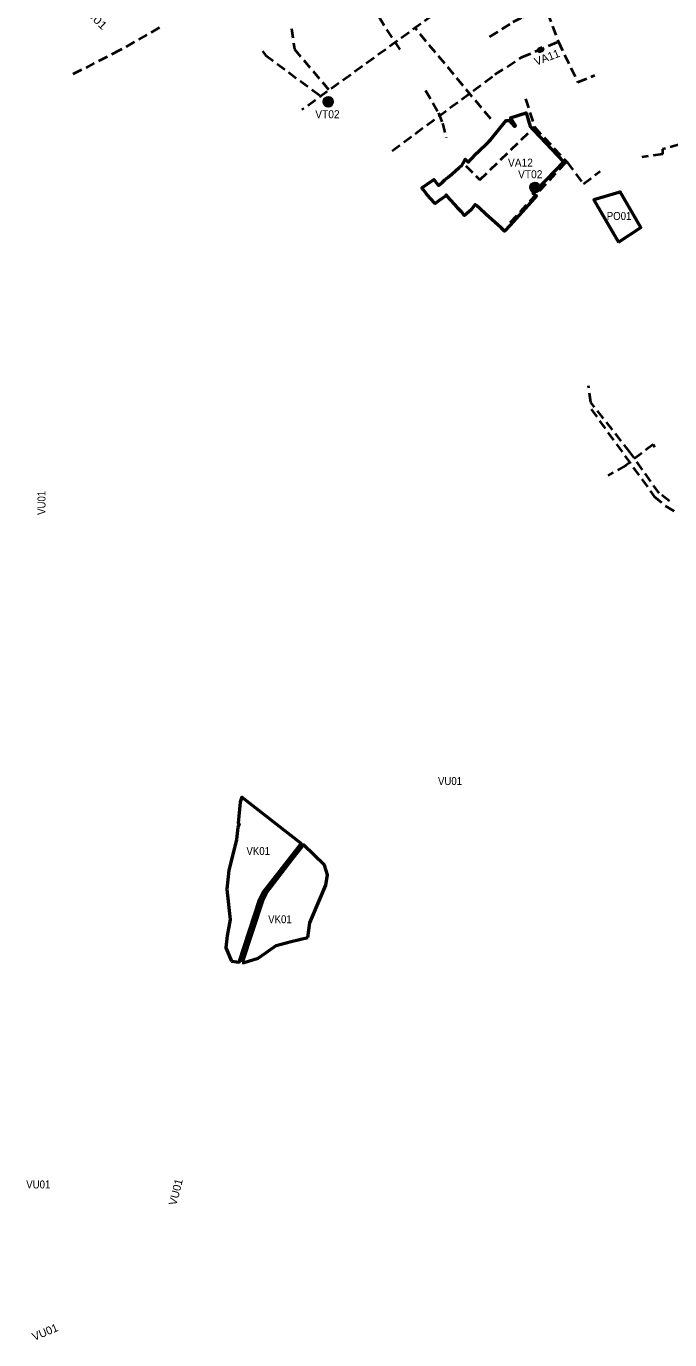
# Model space of a CAD drawing. Extents: x -650145 to -642675, y -1074338 to -1066803.
# Drawn here: x -648976 to -647369, y -1074338 to -1071056 of the extents above; entities that cross this region are included whole.
import ezdxf

# ---------------------------------------------------------------- set-up
doc = ezdxf.new("R2010")
doc.units = 0
doc.header["$LTSCALE"] = 8
doc.linetypes.add('MEDIUM_DASHED', pattern=[4.5, 3, -1.5])
for name, color, linetype in [('1', 7, 'Continuous'), ('17', 7, 'Continuous'), ('2', 7, 'Continuous'), ('3', 7, 'Continuous'), ('4', 7, 'Continuous')]:
    doc.layers.add(name, color=color, linetype=linetype)
for name, color, linetype, lineweight in [('12', 7, 'MEDIUM_DASHED', 40), ('15', 7, 'Continuous', 13), ('45', 7, 'Continuous', 53), ('46', 7, 'Continuous', 53), ('60', 7, 'Continuous', 53)]:
    doc.layers.add(name, color=color, linetype=linetype, lineweight=lineweight)

msp = doc.modelspace()

# ---------------------------------------------------------------- hatches: boundary and pattern name
at = {"layer": '15'}
for points in [[(-648210.363, -1071245, 1), (-648233.888, -1071245, 1)], [(-647694.212, -1071458.99, 1), (-647717.737, -1071458.99, 1)]]:
    msp.add_hatch(color=256, dxfattribs=at).paths.add_polyline_path(points)
at = {"layer": '60'}
msp.add_hatch(color=256, dxfattribs=at).paths.add_polyline_path([(-647687.68, -1071110.18), (-647696.64, -1071114.02), (-647694.63, -1071118.73), (-647685.66, -1071114.89)])

# ---------------------------------------------------------------- linework, layer by layer
at = {"layer": '12'}
for p, q in [((-648042.555, -1071114.098), (-648099.428, -1071026.867)), ((-647815.949, -1071287.658), (-648004.905, -1071060.503)), ((-647767.223, -1071546.187), (-647626.359, -1071394.366))]:
    msp.add_line(p, q, dxfattribs=at)
for points in [[(-647794.16, -1070745.19), (-647787.83, -1070767.157), (-647743.987, -1070862.016), (-647758.284, -1070869.702), (-647784.836, -1070875.103), (-647850.393, -1070906.456), (-647898.698, -1070936.31), (-647903.521, -1070987.043), (-648287.54, -1071265.293)], [(-647818.707, -1071082.607), (-647759.543, -1071045.17), (-647733.735, -1071032.504), (-647710.774, -1071025.971), (-647674.039, -1071022.323), (-647646.98, -1071094.735)], [(-648643.705, -1071059.314), (-648742.207, -1071116.062), (-648865.074, -1071178.477)], [(-648313.283, -1071061.443), (-648306.336, -1071112.945), (-648219.799, -1071215.376)], [(-648062.403, -1071367.342), (-647805.426, -1071176.999), (-647738.219, -1071133.017), (-647646.98, -1071094.735), (-647598.326, -1071195.826), (-647556.251, -1071178.604)], [(-648386.1, -1071118.4), (-648378.803, -1071128.097), (-648240.257, -1071231.033)], [(-647978.731, -1071216.254), (-647946.561, -1071272.093), (-647936.852, -1071298.253), (-647926.931, -1071334.225)], [(-647728.988, -1071237.115), (-647707.004, -1071307.776), (-647625.351, -1071395.71), (-647584.501, -1071450.177), (-647542.285, -1071418.425)], [(-647878.3, -1071404.7), (-647843.135, -1071439.808), (-647707.004, -1071307.776)], [(-647344.33, -1071351.49), (-647386.85, -1071363.37), (-647386.8, -1071375.58), (-647438.34, -1071382.93)], [(-647369.65, -1072242.58), (-647395.603, -1072222.827), (-647467.645, -1072120.835), (-647565.59, -1071996.178), (-647571.937, -1071954.126)], [(-647565.274, -1072012.581), (-647407.42, -1072230.889), (-647378.312, -1072255.368), (-647327.486, -1072284.458), (-647289.597, -1072293.583), (-647241.628, -1072293.997), (-647186.201, -1072273.818), (-647145.51, -1072238.04)], [(-647405.694, -1072108.1), (-647409.897, -1072100.921), (-647478.896, -1072153.329), (-647523.403, -1072178.874)]]:
    msp.add_lwpolyline(points, dxfattribs=at)
at = {"layer": '15', "lineweight": 35}
for centre in [(-648222.125, -1071245), (-647705.974, -1071458.99)]:
    msp.add_circle(centre, 11.762, dxfattribs=at)
at = {"layer": '45'}
for points in [[(-648463.25, -1073392.125), (-648444.523, -1073394.235), (-648392.43, -1073235.98), (-648384.6, -1073219.54), (-648315.955, -1073131.889), (-648289.148, -1073097.66), (-648437.643, -1072982.601), (-648442.187, -1072994.5), (-648447.043, -1073046.967), (-648444.11, -1073048.69), (-648448.1, -1073058.393)], [(-648448.1, -1073058.393), (-648450.875, -1073088.375), (-648469.875, -1073165.5), (-648475.437, -1073212.375), (-648466.687, -1073288.25), (-648474.5, -1073328.75), (-648477.562, -1073358.875), (-648463.25, -1073392.125)], [(-648272.642, -1073332.558), (-648268, -1073296), (-648261, -1073280), (-648228, -1073202), (-648224, -1073176), (-648231, -1073152), (-648283.884, -1073101.15), (-648311.798, -1073137.127), (-648378.17, -1073222.67), (-648385.09, -1073238.58), (-648436.857, -1073395.099)], [(-648397.062, -1073384.375), (-648378.125, -1073370.875), (-648352.312, -1073353), (-648314.687, -1073343.25), (-648272.642, -1073332.558)], [(-648436.857, -1073395.099), (-648432.187, -1073395.625), (-648397.062, -1073384.375)]]:
    msp.add_lwpolyline(points, dxfattribs=at)
at = {"layer": '46'}
msp.add_lwpolyline([(-647497.04, -1071595.66), (-647440.67, -1071558.93), (-647492.3, -1071470), (-647495.85, -1071471.06), (-647558.654, -1071489.738)], close=True, dxfattribs=at)
at = {"layer": '60'}
for points in [[(-647687.68, -1071110.18), (-647696.64, -1071114.02), (-647694.63, -1071118.73), (-647685.66, -1071114.89)], [(-647777.4, -1071291.32), (-647777.4, -1071291.32), (-647774.14, -1071291.34), (-647769.85, -1071291.91), (-647756.67, -1071306.77), (-647753.89, -1071303.94), (-647766.35, -1071285.11), (-647727.368, -1071272.362), (-647717.363, -1071306.29), (-647708.429, -1071316.821), (-647634.524, -1071394.901), (-647700.078, -1071462.96), (-647710.546, -1071472.023), (-647704.78, -1071477.1), (-647701.415, -1071480.15), (-647708.18, -1071487.57), (-647767.575, -1071553.083), (-647781.31, -1071567.79), (-647789.73, -1071560.1), (-647828.024, -1071525.256), (-647844.4, -1071510.2), (-647850.55, -1071505.14), (-647855.23, -1071501.297), (-647860.576, -1071508.843), (-647864.69, -1071514.65), (-647869.922, -1071519.269), (-647876.29, -1071524.89), (-647881.16, -1071529.25), (-647883.31, -1071526.83), (-647889.29, -1071520.11), (-647897.27, -1071511.15), (-647905.25, -1071502.19), (-647917.23, -1071488.75), (-647927.2, -1071477.54), (-647929.26, -1071480.77), (-647931.17, -1071482.12), (-647936.59, -1071485.96), (-647944.81, -1071491.78), (-647955.14, -1071499.23), (-647967.13, -1071486.01), (-647972.76, -1071479), (-647977.13, -1071474.05), (-647984.07, -1071465.1), (-647987.8, -1071459.68), (-647961.4, -1071441.47), (-647957.906, -1071439.06), (-647946.78, -1071454.23), (-647937.43, -1071446.16), (-647930.38, -1071440.08), (-647921.96, -1071432.81), (-647913.31, -1071425.35), (-647904.3, -1071417.58), (-647895.29, -1071409.81), (-647888.11, -1071403.61), (-647885.05, -1071397.88), (-647879.76, -1071387.96), (-647871.68, -1071395.59), (-647867.45, -1071390.95), (-647849.86, -1071372.18), (-647820.93, -1071344.25), (-647815.474, -1071339.22)]]:
    msp.add_lwpolyline(points, close=True, dxfattribs=at)

# ---------------------------------------------------------------- texts
at = {"layer": '1', "width": 0.9}
for p in [(-648426.286, -1073126.802), (-648372.004, -1073297.285)]:
    msp.add_text('VK01', height=20, dxfattribs=at).set_placement(p)
at = {"layer": '17', "width": 0.95}
for p in [(-648254.236, -1071285.892), (-647747.641, -1071435.784)]:
    msp.add_text('VT02', height=20, dxfattribs=at).set_placement(p)
at = {"layer": '2'}
for rotation, width, p in [(315.876, 1.2, (-648843.543, -1071010.613)), (90, 0.9, (-648928.323, -1072276.985))]:
    msp.add_text('VU01', height=20, rotation=rotation, dxfattribs=dict(at, width=width)).set_placement(p)
at = {"layer": '2', "width": 0.9}
for p in [(-647947.746, -1072951.906), (-648976.371, -1073959.861)]:
    msp.add_text('VU01', height=20, dxfattribs=at).set_placement(p)
at = {"layer": '2'}
for rotation, p in [(75.792, (-648601.32, -1074003.735)), (22.398, (-648956.62, -1074340.801))]:
    msp.add_text('VU01', height=20, rotation=rotation, dxfattribs=at).set_placement(p)
at = {"layer": '3'}
msp.add_text('VA11', height=20, rotation=20.894, dxfattribs=at).set_placement((-647702.554, -1071154.847))
at = {"layer": '3', "width": 0.95}
msp.add_text('VA12', height=20, dxfattribs=at).set_placement((-647772.908, -1071406.958))
at = {"layer": '4', "width": 0.9}
msp.add_text('PO01', height=20, dxfattribs=at).set_placement((-647526.167, -1071540.041))

doc.saveas('drawing.dxf')
